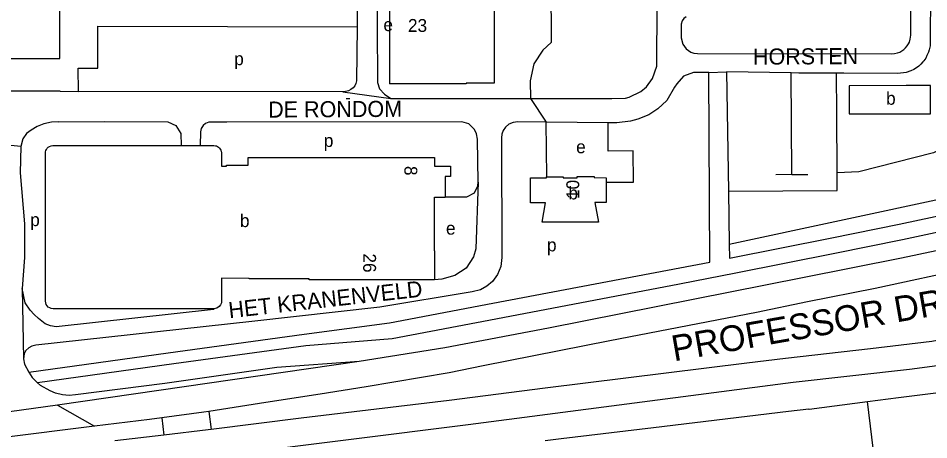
# Model space of a CAD drawing. Extents: x 161494 to 163033, y 383688 to 384862.
# Drawn here: x 162234.2 to 162517.1, y 384072.6 to 384203.6 of the extents above; entities that cross this region are included whole.
import ezdxf

# ---------------------------------------------------------------- set-up
doc = ezdxf.new("R2010")
doc.units = 0
for name, color, linetype in [('BLT_Basislijn', 7, 'Continuous'), ('BLT_Bebouwing', 7, 'Continuous'), ('BLT_Centroide', 7, 'Continuous'), ('BLT_Huisnummer', 7, 'Continuous'), ('BLT_Huisnummer_reeks', 7, 'Continuous'), ('BLT_Straatnaam', 7, 'Continuous'), ('BLT_Straatnaam_hoofdweg', 7, 'Continuous'), ('BLT_Vlakafsluiter', 7, 'Continuous')]:
    doc.layers.add(name, color=color, linetype=linetype)

msp = doc.modelspace()

# ---------------------------------------------------------------- linework, layer by layer
at = {"layer": 'BLT_Basislijn'}
for p, q in [((162339.55, 384205.93), (162339.49, 384200.93)), ((162339.49, 384200.93), (162339.3, 384184.13)), ((162474.55, 384154.97), (162474.38, 384186.58)), ((162488.53, 384173.81), (162488.44, 384186.49)), ((162247.24, 384180.87), (162227.98, 384180.87)), ((162247.24, 384180.87), (162252.93, 384180.79)), ((162488.64, 384155.57), (162488.53, 384173.81)), ((162398.47, 384154.31), (162398.22, 384171.26)), ((162455.1, 384133.3), (162605.96, 384165.77)), ((162474.55, 384154.97), (162479.54, 384155.02)), ((162474.55, 384154.97), (162469.56, 384154.93)), ((162454.84, 384149.85), (162455.1, 384133.3)), ((162479.84, 384082.1), (162473.58, 384081.34)), ((162479.84, 384082.1), (162479.98, 384082.11)), ((162278.84, 384079.4), (162279.49, 384074.03)), ((162293.46, 384081.38), (162294.15, 384075.74)), ((162473.58, 384081.34), (162431.63, 384076.29)), ((162431.63, 384076.29), (162402.95, 384072.84)), ((162402.95, 384072.84), (162397.98, 384072.25))]:
    msp.add_line(p, q, dxfattribs=at)
for points in [[(162393.39, 384178.59), (162418.62, 384178.59), (162422.93, 384178.75), (162424.04, 384179.07), (162427.66, 384180.76), (162429.39, 384182.25), (162431.25, 384184.79), (162432.65, 384188.67), (162432.92, 384246.22), (162432.89, 384249.86)], [(162247.21, 384191.05), (162247.31, 384229.25), (162106.92, 384229), (162106.81, 384205.82), (162098.37, 384205.81), (162098.37, 384197.75), (162041.94, 384197.72), (162041.92, 384191.05), (162247.21, 384191.05)], [(162441.69, 384203.97), (162440.99, 384203.51), (162440.45, 384202.79), (162440.18, 384201.74), (162440.17, 384197.48), (162440.75, 384195.51), (162441.75, 384194.04), (162443.21, 384193.04), (162444.15, 384192.74), (162445.25, 384192.62), (162505.61, 384192.52), (162506.41, 384192.57), (162507.39, 384192.79), (162508.08, 384193.06), (162508.69, 384193.39), (162509.37, 384193.84), (162509.92, 384194.39), (162510.42, 384194.96), (162510.81, 384195.61), (162511.1, 384196.18), (162511.34, 384197.05), (162511.51, 384198.35), (162511.63, 384221.97)], [(162345.7, 384218.91), (162345.81, 384183.55), (162346.45, 384181.61), (162348.03, 384179.98), (162349.96, 384178.59)], [(162382.1, 384218.67), (162398.31, 384218.7), (162399.75, 384214.3), (162399.76, 384196.07), (162397.26, 384193.6), (162394.39, 384189.44), (162393.3, 384184.07), (162393.39, 384178.59)], [(162517.61, 384211.61), (162517.58, 384196.53), (162517.49, 384194.95), (162517.26, 384193.77), (162517.01, 384192.99), (162516.54, 384191.95), (162516.21, 384191.16), (162515.62, 384190.32), (162515.24, 384189.97), (162514.68, 384189.27), (162514.02, 384188.69), (162513.3, 384188.16), (162512.44, 384187.63), (162511.53, 384187.19), (162510.1, 384186.7)], [(162252.93, 384180.79), (162252.92, 384188), (162258.97, 384188.03), (162259, 384201.08), (162339.49, 384200.93)], [(162582.67, 384197.29), (162534.92, 384170.11), (162518.61, 384161.72), (162495.34, 384155.87), (162488.64, 384155.57)], [(162237.56, 384093.54), (162280.85, 384099.55), (162323.03, 384105.39), (162349.55, 384108.86), (162381.64, 384114.97), (162449.09, 384127.8), (162448.78, 384186.65)], [(162448.78, 384186.65), (162443.98, 384186.69), (162440.96, 384185.59), (162438.8, 384183.2), (162438.16, 384182.12), (162435.69, 384178.02), (162432.95, 384175.41), (162430.12, 384173.5), (162426.75, 384172.15), (162424.41, 384171.56), (162420.22, 384171.04), (162417.55, 384171.06)], [(162448.78, 384186.65), (162454.24, 384186.94)], [(162454.24, 384186.94), (162454.84, 384149.85)], [(162474.38, 384186.58), (162454.24, 384186.94)], [(162476.69, 384186.53), (162474.38, 384186.58)], [(162483.71, 384186.51), (162476.69, 384186.53)], [(162488.44, 384186.49), (162483.71, 384186.51)], [(162490.74, 384186.49), (162488.44, 384186.49)], [(162510.1, 384186.7), (162507.54, 384186.41), (162490.74, 384186.49)], [(162339.3, 384184.13), (162339.11, 384183.33), (162338.77, 384182.6), (162338.28, 384181.96), (162337.62, 384181.4), (162336.83, 384181.05), (162335.96, 384180.82), (162335.07, 384180.73)], [(162335.07, 384180.73), (162252.93, 384180.79)], [(162349.96, 384178.59), (162382.05, 384178.59)], [(162382.05, 384178.59), (162393.39, 384178.59)], [(162246.66, 384171.32), (162244.57, 384171.23), (162242.25, 384170.74), (162240.18, 384169.97), (162238.23, 384168.79), (162236.85, 384167.7), (162235.68, 384166.13), (162235.09, 384163.69)], [(162398.22, 384171.26), (162389.4, 384171.35), (162388.05, 384171.21), (162386.67, 384170.63), (162385.58, 384169.7), (162384.89, 384168.68), (162384.53, 384167.57), (162384.4, 384166.4), (162384.51, 384129.16), (162384.21, 384126.4), (162383.18, 384123.94), (162381.61, 384121.76), (162379.86, 384120.29), (162377.85, 384119.2), (162375.22, 384118.52), (162346.6, 384113.72), (162306.78, 384109.36), (162239.69, 384101.95), (162238.43, 384101.68), (162237.52, 384101.12), (162236.64, 384100.29), (162236.11, 384099.23), (162235.86, 384097.71)], [(162246.66, 384171.32), (162260.9, 384171.47), (162280.7, 384171.36), (162283.26, 384170.27), (162284.8, 384167.79), (162284.85, 384163.98)], [(162299.01, 384171.3), (162293.45, 384171.27), (162292.45, 384170.87), (162291.65, 384170.27), (162291.05, 384169.28), (162290.85, 384168.28), (162290.81, 384163.98)], [(162377.14, 384152.59), (162376.91, 384166.01), (162376.62, 384167.62), (162375.98, 384168.95), (162374.26, 384170.73), (162372.09, 384171.36), (162299.01, 384171.3)], [(162417.55, 384171.06), (162398.22, 384171.26)], [(162416.84, 384152.65), (162425.37, 384152.67), (162425.3, 384162.33), (162417.54, 384162.29), (162417.55, 384171.06)], [(162235.09, 384163.69), (162234.86, 384155.5), (162236.15, 384139.66), (162236.2, 384129.17), (162235.44, 384119.61)], [(162454.84, 384149.85), (162488.67, 384150.05), (162488.64, 384155.57)], [(162377.14, 384152.59), (162376.41, 384131.9), (162375.68, 384129.41), (162373.43, 384125.88), (162369.88, 384123.65), (162365.87, 384122.45), (162363.56, 384122.26)], [(162366.87, 384148.04), (162373.58, 384148.07), (162375.99, 384149.28), (162376.98, 384151.47), (162377.14, 384152.59)], [(162617.42, 384153.51), (162602.88, 384149.84), (162581.77, 384144.63), (162567.69, 384140.96), (162538.93, 384135.45), (162508.64, 384129.02)], [(162568.26, 384147.43), (162536.97, 384140.69), (162508.97, 384134.72)], [(162455.1, 384133.3), (162455.17, 384129), (162486.94, 384135.33), (162507.91, 384139.6), (162535.12, 384145.41)], [(162508.97, 384134.72), (162487.93, 384130.43), (162457.17, 384124.3), (162439.72, 384120.93)], [(162508.64, 384129.02), (162477.88, 384122.89), (162398.94, 384107.28)], [(162530.17, 384125.97), (162500.45, 384119.61), (162479.46, 384115.38), (162463.55, 384112.14)], [(162295.07, 384113.3), (162294.95, 384113.08), (162246.08, 384107.69), (162244.3, 384107.96), (162242.65, 384108.6), (162240.6, 384110.21), (162239.2, 384111.47), (162237.99, 384112.81), (162236.44, 384115.09), (162235.44, 384119.61)], [(162439.72, 384120.93), (162382.57, 384110.06), (162350.44, 384103.94), (162323.55, 384101.77), (162282.57, 384096.12), (162240.24, 384090.29)], [(162609.51, 384114.25), (162583.17, 384107.55), (162557.51, 384101.52), (162545.68, 384099.29), (162532.96, 384097.28), (162511.09, 384094.38), (162474.93, 384090.36)], [(162463.55, 384112.14), (162418.06, 384103.26), (162378.63, 384095.51), (162368.07, 384093.4)], [(162398.94, 384107.28), (162366.81, 384101.15), (162340.19, 384096.86)], [(162525.24, 384104.42), (162518.05, 384103.12), (162499.04, 384100.87), (162472.56, 384097.77), (162460.59, 384096.36)], [(162235.86, 384097.71), (162236.22, 384096.09)], [(162236.22, 384096.09), (162237.56, 384093.54)], [(162340.19, 384096.86), (162314.61, 384095.04), (162279.79, 384090.02), (162252.06, 384086.5), (162250.06, 384086.31), (162248.02, 384086.53), (162245.79, 384087.01), (162244.16, 384087.73), (162241.14, 384089.42), (162240.24, 384090.29)], [(162460.59, 384096.36), (162397.92, 384088.61), (162368.07, 384084.8)], [(162237.56, 384093.54), (162238.58, 384091.9), (162240.24, 384090.29)], [(162368.07, 384093.4), (162342.3, 384089.03), (162328.07, 384086.77), (162311.17, 384084.1), (162293.46, 384081.38)], [(162474.93, 384090.36), (162374.06, 384077.18), (162263.36, 384063.34)], [(162498.03, 384084.42), (162507.74, 384085.67), (162543.22, 384090.13), (162549.36, 384091.36)], [(162368.07, 384084.8), (162345.54, 384082.12), (162322.16, 384079.3), (162294.15, 384075.74)], [(162473.95, 384047.55), (162502.09, 384051.2), (162498.03, 384084.42)], [(162479.98, 384082.11), (162498.03, 384084.42)], [(162278.84, 384079.4), (162274.98, 384078.88), (162257.94, 384076.77)], [(162293.46, 384081.38), (162291.88, 384081.14), (162278.84, 384079.4)], [(162257.94, 384076.77), (162229.07, 384073.11), (162180.34, 384067.19), (162170.91, 384066.06)], [(162279.49, 384074.03), (162264.28, 384072.26)], [(162294.15, 384075.74), (162293.29, 384075.64), (162279.49, 384074.03)]]:
    msp.add_lwpolyline(points, dxfattribs=at)
at = {"layer": 'BLT_Bebouwing'}
msp.add_line((162363.53, 384131.27), (162363.56, 384122.26), dxfattribs=at)
for points in [[(162349.59, 384218.91), (162349.59, 384183.19)], [(162382.1, 384218.67), (162382.06, 384183.4)], [(162382.06, 384183.4), (162373.4, 384183.38), (162373.4, 384183.2), (162349.59, 384183.19)], [(162510.13, 384182.61), (162492.4, 384182.56), (162492.42, 384173.83)], [(162492.42, 384173.83), (162517.65, 384173.88), (162517.62, 384182.62), (162510.13, 384182.61)], [(162242.73, 384128.29), (162242.73, 384161.62), (162242.77, 384162.09), (162242.87, 384162.43), (162243.03, 384162.79), (162243.28, 384163.17), (162243.58, 384163.47), (162243.92, 384163.69), (162244.45, 384163.9), (162245.05, 384163.97), (162284.85, 384163.98)], [(162284.85, 384163.98), (162290.81, 384163.98)], [(162290.81, 384163.98), (162295.05, 384163.99), (162295.49, 384163.94), (162295.82, 384163.86), (162296.17, 384163.7), (162296.5, 384163.5), (162296.82, 384163.21), (162297.02, 384162.9), (162297.21, 384162.58), (162297.34, 384162.17), (162297.4, 384161.9), (162297.4, 384161.64), (162297.4, 384157.61), (162298.92, 384157.61), (162298.93, 384157.92), (162299, 384157.92)], [(162299, 384157.92), (162305.71, 384157.92), (162305.69, 384160.3), (162363.56, 384160.31), (162363.53, 384157.55), (162364.89, 384157.56), (162368.53, 384157.57), (162368.54, 384154.43), (162366.88, 384154.42), (162366.87, 384148.04)], [(162393.43, 384153.98), (162398.31, 384153.99), (162398.31, 384154.31), (162398.47, 384154.31)], [(162416.84, 384152.65), (162416.87, 384146.29), (162413.41, 384146.27), (162414.46, 384140.19), (162397.05, 384140.16), (162398.07, 384146.16), (162393.43, 384146.16), (162393.43, 384153.98)], [(162398.47, 384154.31), (162403.54, 384154.32), (162403.54, 384154), (162407.9, 384154.01), (162407.9, 384154.33), (162413.14, 384154.35), (162413.14, 384154.03), (162416.84, 384154), (162416.84, 384152.65)], [(162363.53, 384131.27), (162363.54, 384147.98), (162366.87, 384147.99), (162366.87, 384148.04)], [(162295.07, 384113.3), (162245.07, 384113.3), (162244.52, 384113.35), (162244.03, 384113.53), (162243.6, 384113.81), (162243.22, 384114.18), (162242.96, 384114.63), (162242.79, 384115.12), (162242.73, 384115.62), (162242.73, 384128.29)], [(162297.41, 384122.75), (162297.4, 384115.65), (162297.38, 384115.07), (162297.11, 384114.47), (162296.66, 384113.93), (162295.99, 384113.46), (162295.07, 384113.3)], [(162363.56, 384122.26), (162324.63, 384122.29), (162324.63, 384122.57), (162306.02, 384122.6), (162306.02, 384122.73), (162297.41, 384122.75)]]:
    msp.add_lwpolyline(points, dxfattribs=at)
at = {"layer": 'BLT_Vlakafsluiter'}
for p, q in [((162335.07, 384180.73), (162349.96, 384178.59)), ((162336.14, 384178.65), (162337.22, 384178.65)), ((162393.39, 384178.59), (162398.22, 384171.26)), ((162235.09, 384163.69), (162227.52, 384164.46)), ((162340.19, 384096.86), (162246.45, 384083.27)), ((162246.45, 384083.27), (162212.3, 384078.63)), ((162246.45, 384083.27), (162257.94, 384076.77))]:
    msp.add_line(p, q, dxfattribs=at)
msp.add_lwpolyline([(162235.44, 384119.61), (162235.86, 384097.71)], dxfattribs=at)

# ---------------------------------------------------------------- texts
at = {"layer": 'BLT_Centroide'}
for s, p in [('e', (162347.69, 384199.58)), ('p', (162301.34, 384188.98)), ('b', (162503.84, 384176.68)), ('p', (162329.18, 384163.55)), ('e', (162407.56, 384161.61)), ('b', (162405.15, 384147.25)), ('p', (162237.97, 384138.96)), ('b', (162303.13, 384138.66)), ('e', (162367.13, 384136.31)), ('p', (162398.51, 384131.11))]:
    msp.add_text(s, height=4, dxfattribs=at).set_placement(p)
at = {"layer": 'BLT_Huisnummer'}
for s, rotation, p in [('8', 269.8564, (162354.22, 384157.66)), ('10', 90.0482, (162408.52, 384147.38)), ('26', 269.8564, (162341.42, 384130.48))]:
    msp.add_text(s, height=4, rotation=rotation, dxfattribs=at).set_placement(p)
at = {"layer": 'BLT_Huisnummer_reeks'}
msp.add_text('23', height=4, rotation=359.77, dxfattribs=at).set_placement((162355.31, 384199.33))
at = {"layer": 'BLT_Straatnaam'}
for s, rotation, p in [('HORSTEN', 0.3445, (162462.5, 384189.12)), ('DE RONDOM', 0.3445, (162311.9, 384172.68)), ('HET KRANENVELD', 6.4105, (162299.85, 384110.32))]:
    msp.add_text(s, height=5, rotation=rotation, dxfattribs=at).set_placement(p)
at = {"layer": 'BLT_Straatnaam_hoofdweg'}
msp.add_text('PROFESSOR DR DORGELOLAAN', height=8, rotation=9.9281, dxfattribs=at).set_placement((162437.96, 384096.91))

doc.saveas('drawing.dxf')
